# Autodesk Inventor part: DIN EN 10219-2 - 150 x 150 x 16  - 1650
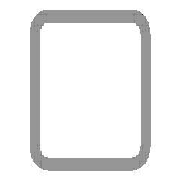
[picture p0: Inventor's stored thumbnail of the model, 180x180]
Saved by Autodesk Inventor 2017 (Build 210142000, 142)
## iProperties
Created: 2017-11
Part Number: DIN EN 10219-2 - 150 x 150 x 16  - 1650
Material: Steel, Mild
Description: Cold formed welded structural hollow sections of non-alloy and fine grain structural steel
Document SubType Name: Modeling
Standard: DIN
Designer: iusti
Standard Revision: 2006-07
Standards Organization: DIN
Language: en-US
Size Designation: 150 x 150 x 16
Categories: <MemberInstance><Categories><Category DisplayName="Structural Shapes" InternalName="089c4875-fa83-4c05-b084-43b9cc11f5ed" Mnemonic="GRDR"><CategoryParameter Dis
Stock Number: 150 x 150 x 16
Density: 7.85 g/cm^3
Appearance: Semi-Polished
Mass: 88044.5 g
Surface Area: 14231.3 cm^2
Volume: 11215.9 cm^3
G_L: 1650.000 mm
G_W: 150.000 mm
G_H: 150.000 mm
+81F2769D-CBCB-4BAE-9991-99821565208A+CUTDETAIL1: Miter 45.00 deg
+00569EB8-A9A7-487F-AD20-8A8F135713C5+CUTDETAIL2: Miter 45.00 deg
_CCFamilyMember: 76
_CCFamilyDisplayName: DIN EN 10219-2 (Square Hollow Section - Cold Formed) - Cold formed welded structural hollow sections of non-alloy and fine grain structural steel
_FrameMemberDoc: Frame Member File
_Version: 15.0.0
_GetPNFromCC: 1
Author: iusti
IsCustomPart: 1
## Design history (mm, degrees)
node "Start plane"
node "End plane"
sketch "Sketch"
  geometry: L1 (-75, -27)-(-75, 27); L2 (-27, 75)-(27, 75); L3 (75, 27)-(75, -27); L4 (27, -75)-(-27, -75); L5 (-27, 59)-(27, 59); L6 (59, 27)-(59, -27); L7 (27, -59)-(-27, -59); L8 (-59, -27)-(-59, 27); L9 (0, 118.918)-(0, -118.918) reference; L10 (-118.918, 0)-(118.918, 0) reference; A1 r 48 centre (-27, -27) between (-75, -27) and (-27, -75); A2 r 48 centre (-27, 27) between (-27, 75) and (-75, 27); A3 r 48 centre (27, 27) between (75, 27) and (27, 75); A4 r 48 centre (27, -27) between (27, -75) and (75, -27); A5 r 32 centre (-27, 27) between (-27, 59) and (-59, 27); A6 r 32 centre (27, 27) between (59, 27) and (27, 59); A7 r 32 centre (27, -27) between (27, -59) and (59, -27); A8 r 32 centre (-27, -27) between (-59, -27) and (-27, -59)
  constraints: 16 end point, 16 point on circle, 8 centre point, 8 tangent, 4 parallel, 3 equal radius, 2 perpendicular, 7 other
  dimensions: "d7" = 48 radius of A1 (= G_IR); "d10" = 150 distance between parallel lines of L2 L4 (= G_H); "d11" = 150 distance between parallel lines of L1 L3 (= G_W); "d12" = 16 distance between parallel lines of L3 L6 (= G_T); "d15" = 75 distance between parallel lines of L2 L10 (= 0.5 x d10); "d16" = 75 distance between parallel lines of L9 L3 (= 0.5 x d11)
extrude "Body" new body sketch "Sketch" stored distance "d3" = 1650 (= G_L); taper "d4" = 0 deg
node "Driven Length"
  sketch "Sketch3"
    geometry: L1 (0, 0)-(10, 0) reference
    constraints: 2 end point, 1 horizontal
  workplane "Work Plane3"
  sketch "Sketch4"
    geometry: L1 (-2, -75)-(12, -75) reference; L2 (-2, 1575)-(12, 1575) reference
    dimensions: "d18" = 1650 distance between parallel lines of L1 L2 (derived)
workplane "Work Plane4"
split "Split1"
workplane "Work Plane5"
split "Split2"
body "Solid1"
other parameters: "G_W" = 150 [user parameter; used in 1 equation term], "G_H" = 150 [user parameter; used in 1 equation term], "G_T" = 16 [user parameter; used in 1 equation term], "G_IR" = 48 [user parameter; used in 1 equation term], "G_L" = 1650 (= d18) [user parameter; used in 1 equation term], "G_OFFSET_START" = 75 [user parameter; used in 1 equation term], "G_OFFSET_END" = 75 [user parameter; used in 1 equation term], "d13" = -75 (= -G_OFFSET_START), "d14" = 1575 (= G_OFFSET_END + B_L), "d17" = 90 deg
